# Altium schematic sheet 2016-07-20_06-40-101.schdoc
size 224 x 111 mm; SheetNumber: 1; SheetTotal: 1
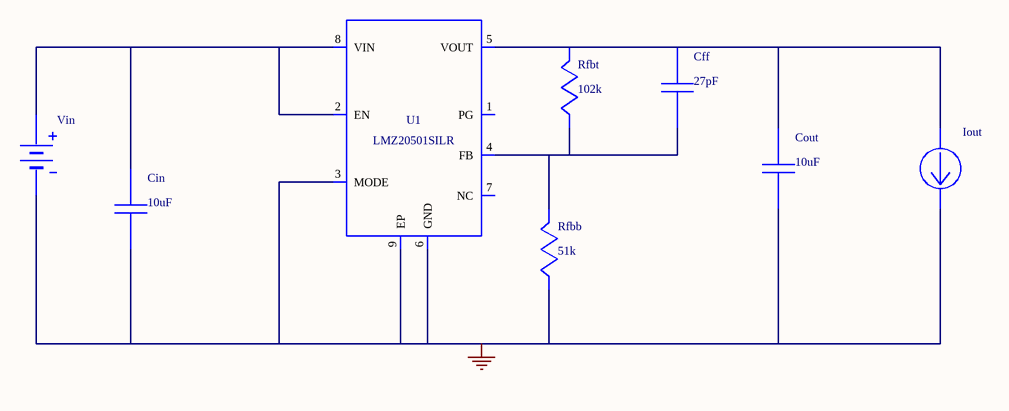
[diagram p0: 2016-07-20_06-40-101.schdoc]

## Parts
Cff  value 27pF  (hidden comment: C0201C270J3GACTU)
Cin  value 10uF  (hidden comment: GRM21BR61C106KE15L)
Cout  value 10uF  (hidden comment: GRM21BR60J106ME19L)
Iout  WB_CURRENT_LOAD  (value not drawn)
Rfbb  value 51k  (hidden comment: RC0603FR-0751KL)
Rfbt  value 102k  (hidden comment: CRCW0402102KFKED)
U1  LMZ20501SILR
Vin  WB_BATTERY  (value not drawn)

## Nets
0: Cin.2 Cout.2 Iout.2(-) Rfbb.2 U1.3(MODE) U1.6(GND) U1.9(EP) Vin.2(-)
NetCff_1: Cff.1 Cout.1 Iout.1(+) Rfbt.1 U1.5(VOUT)
NetCff_2: Cff.2 Rfbb.1 Rfbt.2 U1.4(FB)
NetCin_1: Cin.1 U1.2(EN) U1.8(VIN) Vin.1(+)

Not connected (* = marked no-connect by the designer): U1 1(PG) 7(NC)

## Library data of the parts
Cff = C0201C270J3GACTU: Manufacturer Name: Kemet
Cin = GRM21BR61C106KE15L: GRM21BR61C106KE1; Manufacturer Name: MuRata
Cout = GRM21BR60J106ME19L: GRM21BR60J106ME1; Manufacturer Name: MuRata
Rfbb = RC0603FR-0751KL: Manufacturer Name: Yageo America
Rfbt = CRCW0402102KFKED: Manufacturer Name: Vishay-Dale
U1 = LMZ20501SILR: Manufacturer Name: Texas Instruments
